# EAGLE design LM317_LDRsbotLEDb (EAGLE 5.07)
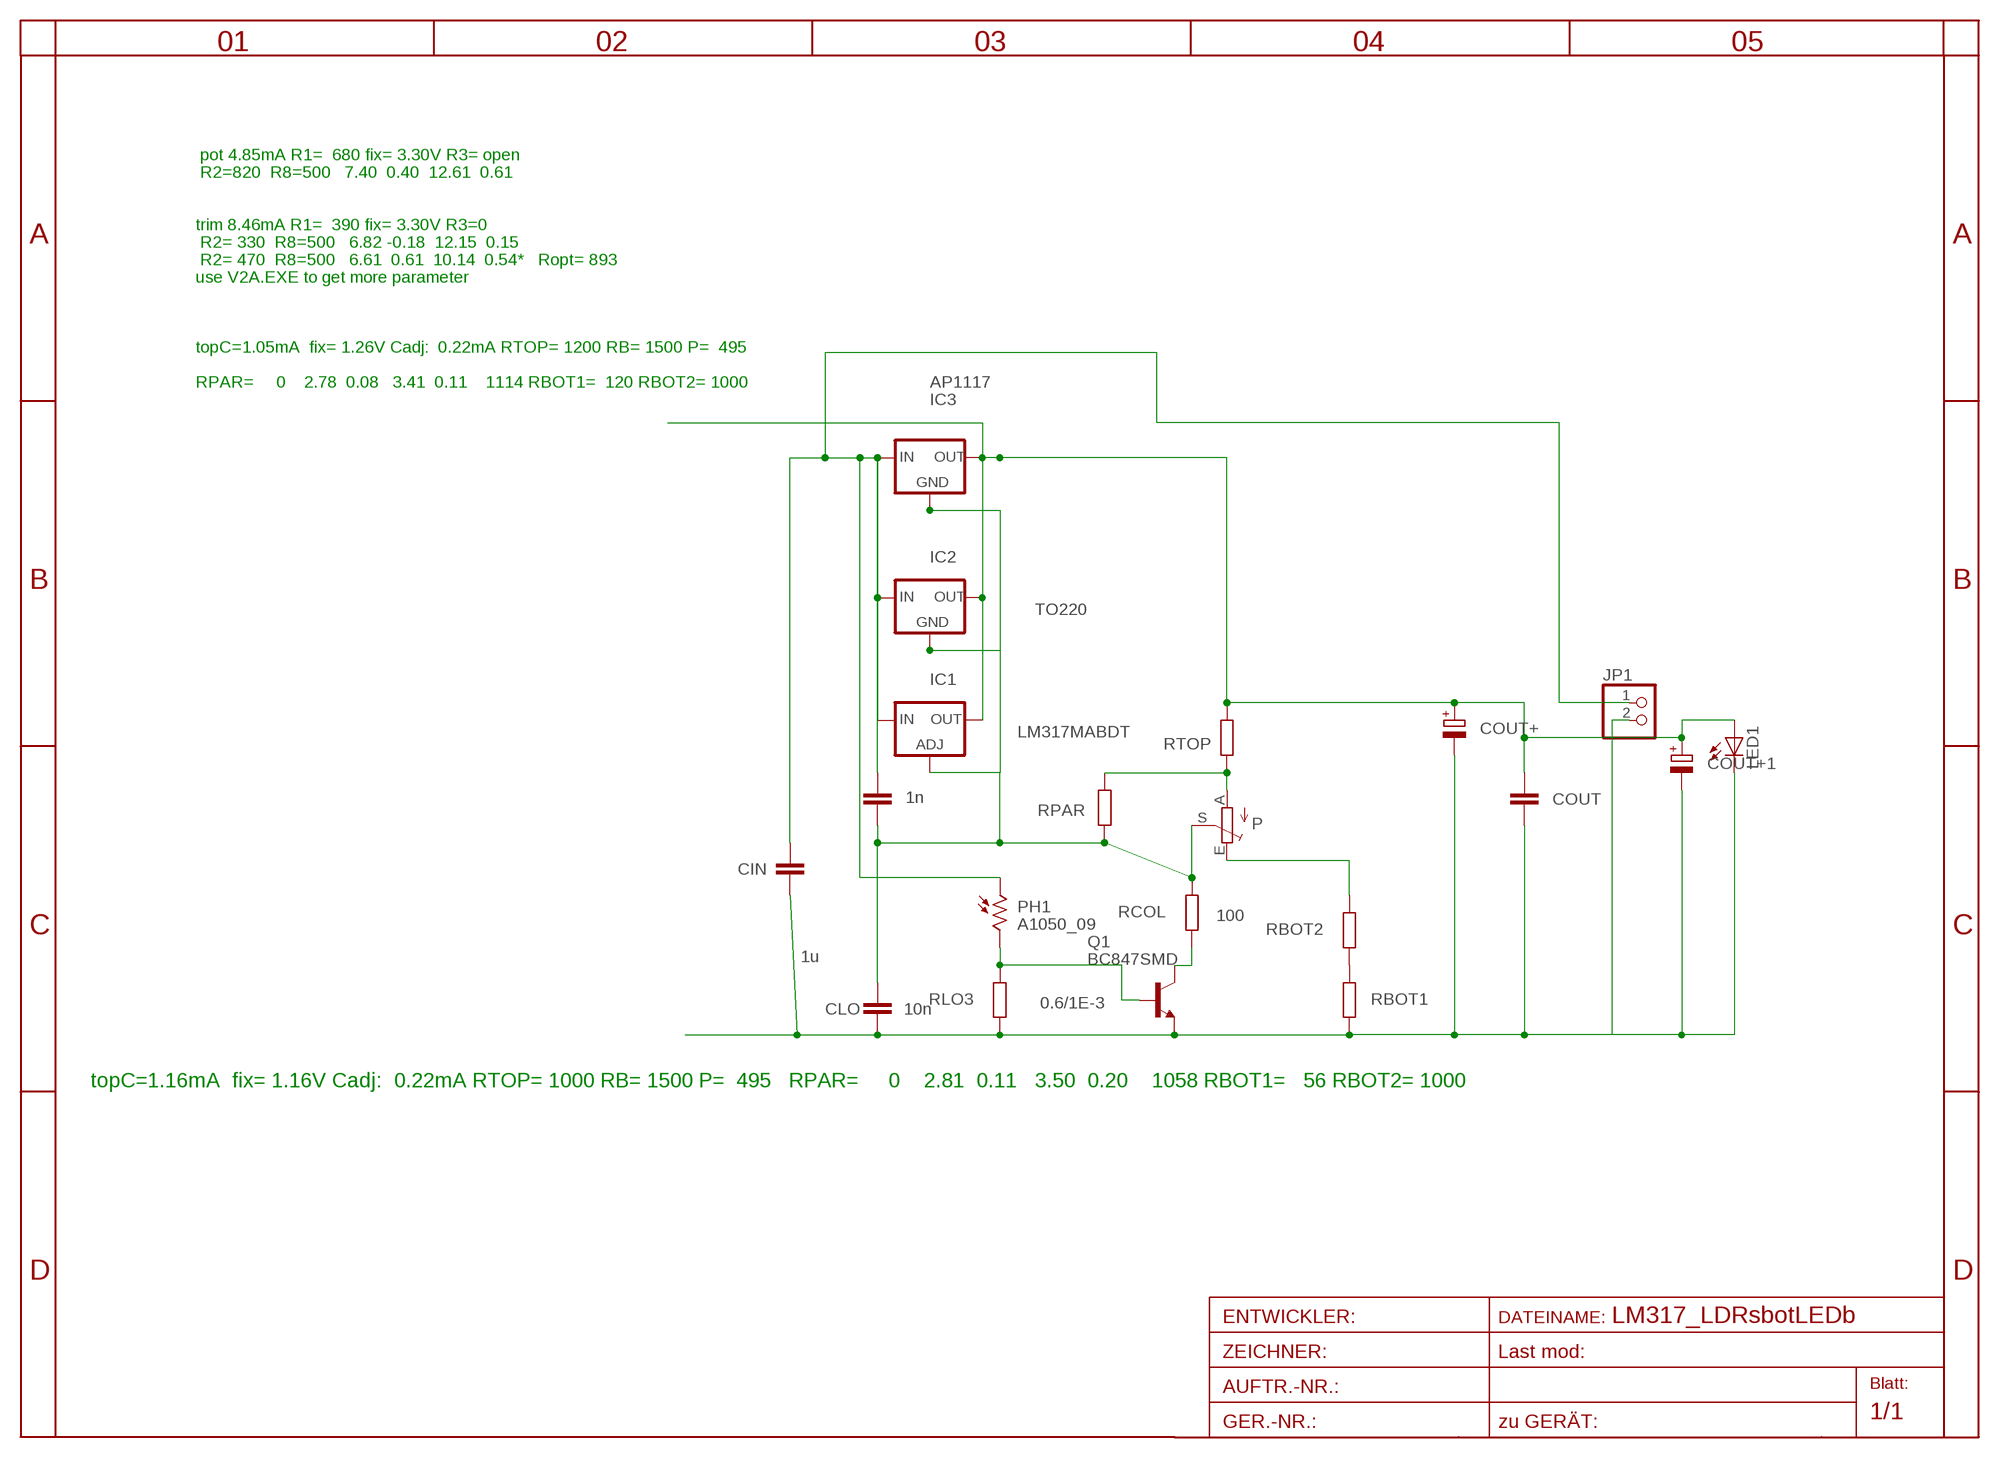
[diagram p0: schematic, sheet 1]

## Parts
CHI  1n  C-EUC0805  [C0805]
CIN  1u  C-EUC1206  [C1206]
CLO  10n  C-EUC0805  [C0805]
COUT  C-EUC1206  [C1206]
COUT+  CPOL-EUE3.5-10  [E3,5-10]
COUT+1  CPOL-EUE7.5-16  [E7,5-16]
IC1  LM317MABDT  [DPACK]
IC2  TO220  78XXS  [78XXS]
IC3  AP1117  [SOT223]
JP1  PINHD-1X2STR  [1X02]
LED1  LED1W_HOLE  [1W]
P  TRIM_EU-RAND160  [RANDL]
PH1  A1050_09  [T0-46-A10XX]
Q1  BC847SMD  [SOT23]
RBOT1  R-EU_R0805  [R0805]
RBOT2  R-EU_R0805  [R0805]
RCOL  100  R-EU_R0805  [R0805]
RLO3  0.6/1E-3  R-EU_R0805  [R0805]
RPAR  R-EU_R0805  [R0805]
RTOP  R-EU_R0805  [R0805]

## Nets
GND: CIN.2 CLO.2 COUT+1.- COUT+.- COUT.2 JP1.2 LED1.C Q1.2(E) RBOT1.1 RLO3.1
IN: CHI.1 CIN.1 IC1.3(IN) IC2.IN IC3.3(IN) JP1.1 PH1.1
N$1: P.E RBOT2.2
N$2: RBOT1.2 RBOT2.1
N$3: Q1.3(C) RCOL.1
N$4: CHI.2 CLO.1 IC1.1(ADJ) IC2.GND IC3.1(GND) P.S RCOL.2 RPAR.1
N$5: PH1.2 Q1.1(B) RLO3.2
N$7: P.A RPAR.2 RTOP.1
OUT: COUT+1.+ COUT+.+ COUT.1 IC1.4(OUT) IC2.OUT IC3.2(OUT) IC3.4(TAB) LED1.A RTOP.2

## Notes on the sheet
- pot 4.85mA R1=  680 fix= 3.30V R3= open
- R2=820  R8=500   7.40  0.40  12.61  0.61
- trim 8.46mA R1=  390 fix= 3.30V R3=0
- R2= 330  R8=500   6.82 -0.18  12.15  0.15
- R2= 470  R8=500   6.61  0.61  10.14  0.54*   Ropt= 893
- use V2A.EXE to get more parameter
- topC=1.05mA  fix= 1.26V Cadj:  0.22mA RTOP= 1200 RB= 1500 P=  495
- RPAR=     0    2.78  0.08   3.41  0.11    1114 RBOT1=  120 RBOT2= 1000
- topC=1.16mA  fix= 1.16V Cadj:  0.22mA RTOP= 1000 RB= 1500 P=  495   RPAR=     0    2.81  0.11   3.50  0.20    1058 RBOT1=   56 RBOT2= 1000

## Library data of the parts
CHI CIN CLO COUT = rcl:C-EU: CAPACITOR, European symbol
COUT+ COUT+1 = rcl:CPOL-EU: POLARIZED CAPACITOR, European symbol
IC1 = v-reg:LM317?*: 500 mA Adjustable Output Positive Voltage Regulator Source: http://www.onsemi.co.jp .. LM317M-D.PDF
IC2 = v-reg:78XXS: VOLTAGE REGULATOR
IC3 = v-reg:AP1117
JP1 = pinhead:PINHD-1X2: PIN HEADER
LED1 = led:LED: LED
P = pot:TRIM_EU-: POTENTIOMETER
PH1 = photo-elements:A10: Sensor Robust Light Sensing Applications
Q1 = transistor-npn:BC847*: NPN Transistor
RBOT1 RBOT2 RCOL RLO3 RPAR RTOP = rcl:R-EU_: RESISTOR, European symbol

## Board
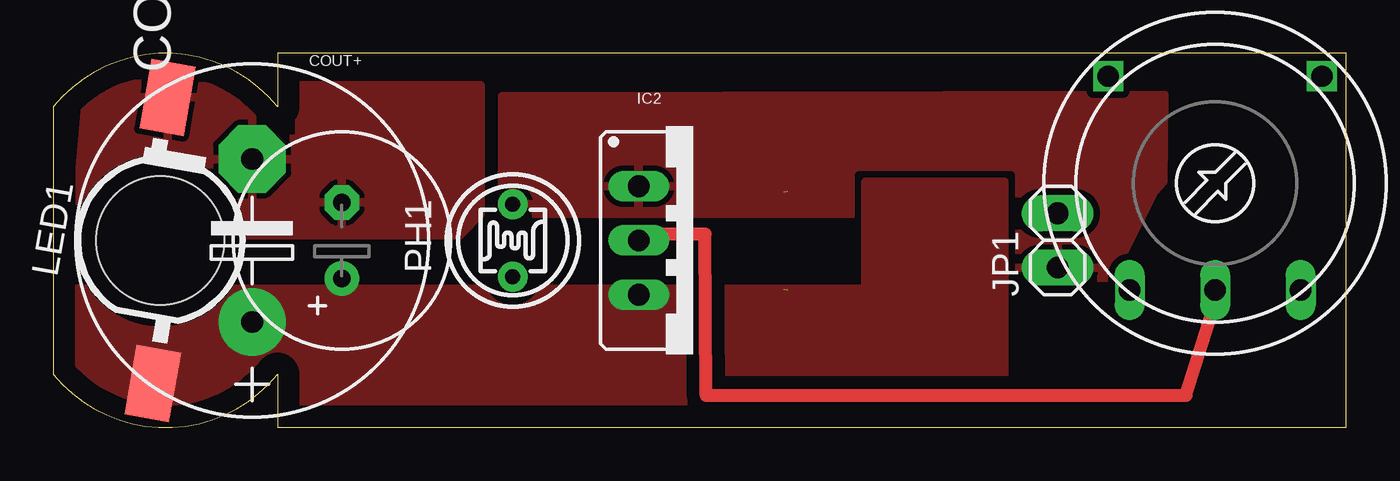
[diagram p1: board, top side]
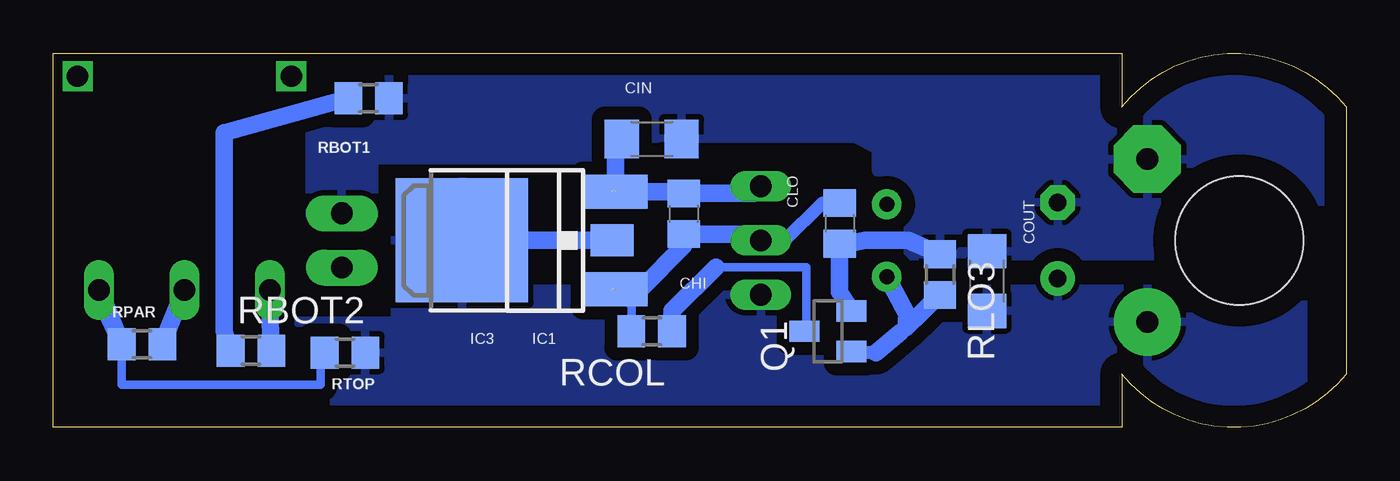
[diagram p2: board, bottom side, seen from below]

Size 60.5 x 17.5 mm. Coordinates in mm from the lower left corner, seen from the top.
Outline: 10.5,0 60.5,0 60.5,17.5 10.5,17.5 10.5,15 arc102 0,15 0,2.5 arc102 10.5,2.5 10.5,0
Copper layers (1*16): Top 0.035mm / dielectric 1.5mm / Bottom 0.035mm
Design rules "default *": minimum track width 10mil, minimum drill 20mil, track to track 8mil, track to pad 8mil, pad to pad 8mil, via to via 8mil, smd to smd 8mil, copper to edge 40mil, drill to drill 8mil, minimum pad ring 8mil, minimum via ring 8mil, stop-mask expansion 8mil, vias tented up to drill 0mil, thermal gap 10mil

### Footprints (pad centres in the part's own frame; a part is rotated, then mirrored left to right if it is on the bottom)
C0805 = smd 1.3 x 1.5: 1 -0.95,0; 2 0.95,0
C1206 = smd 1.6 x 1.8: 1 -1.4,0; 2 1.4,0
E3,5-10 = drill 0.813 pad 1.6 round: + -1.778,0 | drill 0.813 pad 1.6 octagon: - 1.778,0
E7,5-16 = drill 1.016 pad 3.15 round: + -3.81,0 | drill 1.016 pad 3.15 octagon: - 3.81,0
DPACK = smd 1.6 x 3: 1 -2.28,-4.8; 3 2.28,-4.8 | smd 5.8 x 6.2: 4 0,2.38
78XXS = drill 1.016 long: GND 0,-2.54; IN -2.54,-2.54; OUT 2.54,-2.54
SOT223 = smd 1.5 x 2: 1 -2.3,-3.15; 2 0,-3.15; 3 2.3,-3.15 | smd 3.8 x 2: 4 0,3.15
1X02 = drill 1.016 pad 1.676 long: 1 -1.27,0; 2 1.27,0
1W = smd 3.3 x 2.1: A -6.65,-0.82; C 6.65,0.82 | hole 6: 0,0
RANDL = drill 1 long: A -4,5; E 4,5; S 0,5 | drill 1 square: P$1 -5,-5; P$2 5,-5
T0-46-A10XX = drill 0.7 pad 1.4 round: 1 -1.7,0; 2 1.7,0
SOT23 = smd 1 x 1.4: 1 -0.95,-1.1; 2 0.95,-1.1; 3 0,1.1
R0805 = smd 1.3 x 1.5: 1 -0.95,0; 2 0.95,0

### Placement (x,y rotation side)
CHI  31,10 270 bottom
CIN  32.5,13.5 0 bottom
CLO  23.7,9.55 270 bottom
COUT  16.8,6.85 90 bottom
COUT+  13.5,8.75 90 top
COUT+1  9.3,8.75 90 top
IC1  39,8.75 90 bottom
IC2  29.93,8.75 270 top
IC3  37.5,8.75 90 bottom
JP1  47,8.75 90 top
LED1  5,8.75 80 top
P  54.37,11.43 180 top
PH1  21.5,8.75 270 top
Q1  24.25,4.5 90 bottom
RBOT1  45.75,15.4 180 bottom
RBOT2  51.25,3.6 0 bottom
RCOL  32.5,4.5 180 bottom
RLO3  19,7.15 270 bottom
RPAR  56.35,3.9 180 bottom
RTOP  46.85,3.5 0 bottom

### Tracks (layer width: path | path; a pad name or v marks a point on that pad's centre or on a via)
GND
  Bottom 0.813: RLO3.1 20.5,8.75 22.5,8.75 23.8,8.5 CLO.2 23.7,6.35 Q1.2
  pour Bottom (isolate 0.61): 0.5,15.5 arc-92 11,15 11,17.5 48.5,17 48.5,9.5 45.5,9.5 45.5,12.5 35,12.5 32.1,13.55 31,13.5 23,13.5 22,13 22,12 20.5,10.5 20.5,8 0.5,8
  pour Top (isolate 0.406, rank 3): 1.5,15 arc-78 10,15 10,13.5 11.5,13.5 11.5,16 20,16 20,10 19,9 9,9 6,12 3.5,12 1,9.5
IN  (1 unrouted)
  Bottom 0.813: CIN.1 34.2,13.5 IC1.3 31,11.03 CHI.1 27.73,10.95 IC2.IN
  pour Top (isolate 0.305, rank 2): 52,15.56 52,15.5 51.94,11.5 51.5,11 49.5,7 45,7 45,10 21,10 21,15.5
N$1
  Bottom 0.813: RBOT2.2 50.4,6.46 P.E
N$2
  Bottom 0.813: RBOT2.1 52.5,4.5 52.5,13.8 RBOT1.2
N$3
  Bottom 0.406: 29.5,7.5 25.25,7.5 25.25,4.9 Q1.3
  Bottom 0.813: RCOL.1 31.55,5.45 29.5,7.5
N$4  (1 unrouted)
  Top 0.406: 27.69,9.05 IC2.GND
  Top 0.61: P.S 54.37,5.87 53,1.5 30.55,1.5 30.5,9.05 27.69,9.05
  Bottom 0.406: RCOL.2 33.45,5.72 IC1.1 | IC2.GND 26.25,8.75 | 24.5,10.5 CLO.1
  Bottom 0.61: 26.25,8.75 24.5,10.5
  Bottom 0.813: RPAR.1 54.4,6.4 P.S | IC2.GND 27.69,9.05 CHI.2 31,8.5 33,6.5 34.17,6.5 IC1.1
N$5
  Bottom 0.406: 20.6,4.66 20.85,4.45 | 23.1,3.5 Q1.1
  Bottom 0.61: 22,3.5 23.1,3.5
  Bottom 0.813: RLO3.2 20.6,4.66 20.55,5.31 PH1.2 | 20.85,4.45 22,3.5
N$7
  Bottom 0.406: RTOP.1 48,3.5 48,2 57.3,2 RPAR.2
  Bottom 0.813: P.A 58.34,6.4 RPAR.2 58.2,5.72
OUT
  Bottom 0.813: IC3.2 IC3.4
  pour Bottom (isolate 0.61, rank 2): 38,11.5 44.5,11.5 44.5,5 55,5 55,0.5 2,0.5 2,6.5 38,6.5
  pour Top (isolate 0.61, no thermals): 38,11.5 44.5,11.5 44.5,0 10.5,0 10.5,1.5 arc-67 0.5,1.5 0.5,6.5 38,6.5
